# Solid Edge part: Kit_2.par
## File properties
Sűrűség: 0,000 kg/m^3
Pontosság: 0,990
Author: bmolnar
Last saved by: psaghy
Revision: 78
Username: bmolnar
Dokumentum tartalom típus: 0
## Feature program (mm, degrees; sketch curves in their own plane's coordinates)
base feature "unnamed BaseFeature 1"
sketch for "Furat_1" plane through (0, 0, 39) normal (0, 0, 1) x-axis (0, -1, 0)
  hole centre (-23.25, 23.25) bore radius 3.3235
hole "Furat_1" nominal diameter 8 finite  VBottomAngle = 118 deg
sketch for "unnamed Hole 1" plane through (0, 0, 39) normal (0, 0, 1) x-axis (0, -1, 0)
  hole centre (-23.25, -23.25) bore radius 3.3235
hole "unnamed Hole 1" finite
sketch for "unnamed Hole 2" plane through (0, 0, 39) normal (0, 0, 1) x-axis (0, -1, 0)
  hole centre (23.25, -23.25) bore radius 3.3235
hole "unnamed Hole 2" finite
sketch for "unnamed Hole 3" plane through (0, 0, 39) normal (0, 0, 1) x-axis (0, -1, 0)
  hole centre (23.25, 23.25) bore radius 3.3235
hole "unnamed Hole 3" finite
pattern "unnamed Pattern 1" of "Furat_1", "unnamed Hole 1", "unnamed Hole 2", "unnamed Hole 3"
sketch for "Furat_5" plane through (32.5, 0.0003, 21.2488) normal (1, 0, 0) x-axis (0, 0, -1)
  hole centre (-3.7512, 5.9997) bore radius 5.7225
hole "Furat_5" nominal diameter 13.157 finite  ThreadDepth = 10 mm
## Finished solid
Body 1: solid body, 446 faces, 1036 edges, 651 vertices, 7 internal voids.
  Faces by surface: plane 155, cylinder 135, torus 52, cone 51, sphere 23, spline 21, swept 9
  Edges by curve: line 368, circle 356, curve on surface 286, spline 26
Bounding box of the edges (mm; curved faces can reach further): 65.000 x 65.000 x 56.500, from (-32.5, -32.5, 8) to (32.5002, 32.5, 64.5).
Cylindrical faces by radius (mm): R0.3125 x1, R0.3838 x1, R0.4089 x1, R0.4253 x1, R0.4408 x1, R0.5 x8, R0.5003 x1, R0.5483 x1, R0.5961 x1, R0.615 x1, R0.6311 x1, R0.6362 x1, R0.652 x1, R0.6792 x1, R0.73 x1, R0.7378 x1, R0.7396 x1, R0.9114 x1, R1 x20, R1.0004 x7, R1.001 x6, R1.0014 x8, R1.0015 x1, R1.0026 x1, R1.0394 x1, R1.0539 x1, R1.0734 x1, R1.0987 x1, R1.1871 x1, R1.2561 x1, R1.2722 x2, R1.3621 x1, R1.3711 x1, R1.4 x1, R1.7143 x1, R3.3235 x8, R4 x4, R4.15 x4, R4.5 x1, R5 x2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
Conical faces (half-angle, radius in mm at the cone's reference point): 0.5 deg R18.5 x4, 0.5 deg R22.25 x4, 1.6538 deg R11.75 x1, 3.5477 deg R12.7454 x1, 5.762 deg R10.4 x1, 11.1239 deg R10.0056 x1, 15 deg R18.5156 x1, 15.3654 deg R10.7214 x1, 19.3654 deg R11.1921 x1, 25.0169 deg R14.31 x1, 30 deg R5.1443 x1, 30 deg R11.8557 x2, 30 deg R12.1443 x1, 30 deg R19.5 x1, 31.4296 deg R28.625 x4, 45 deg R2.75 x1, 45 deg R2.825 x1, 45 deg R4.3 x8, 45 deg R6.35 x8, 45 deg R6.72 x1, 45 deg R10.15 x2, 45 deg R15.25 x1, 59 deg R3.3235 x4
Toroidal faces (ring radius, tube radius in mm): R0.4909 r0.5044 x1, R0.5094 r0.5004 x1, R0.8674 r0.5067 x1, R1.4976 r0.5003 x6, R4.3 r0.3 x4, R4.7 r0.3 x1, R6.45 r0.2 x4, R7.15 r0.5 x4, R9.5 r0.5 x1, R9.75 r0.5 x2, R10.3 r0.3 x1, R10.3085 r0.3 x1, R11.4279 r0.25 x1, R12.2464 r0.5 x1, R13.9897 r0.5062 x1, R14.8 r0.2 x1, R17 r2 x1, R17.6163 r0.5 x1, R19.4739 r1 x1, R19.4913 r1 x3, R20.5 r0.5 x1, R21.2587 r1 x3, R21.2761 r1 x1, R27.25 r1 x3, R31.75 r1 x6, R33.3108 r1 x1
Spherical faces by radius (mm): R0.5 x1, R1 x22
Planar faces by outward normal: +x 24, +y 9, +z 36, -x 5, -y 8, -z 24, oblique 49
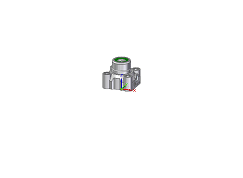
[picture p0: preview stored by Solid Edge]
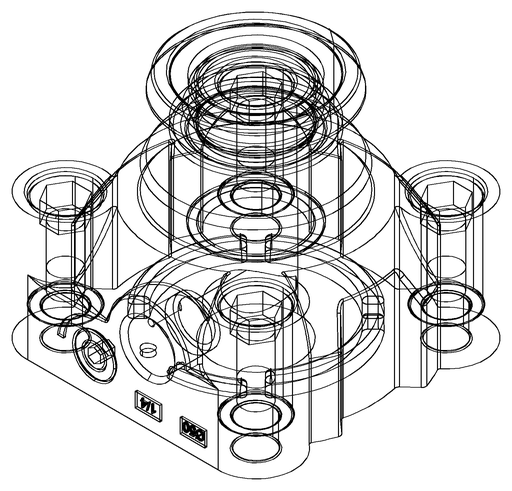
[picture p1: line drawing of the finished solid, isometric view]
